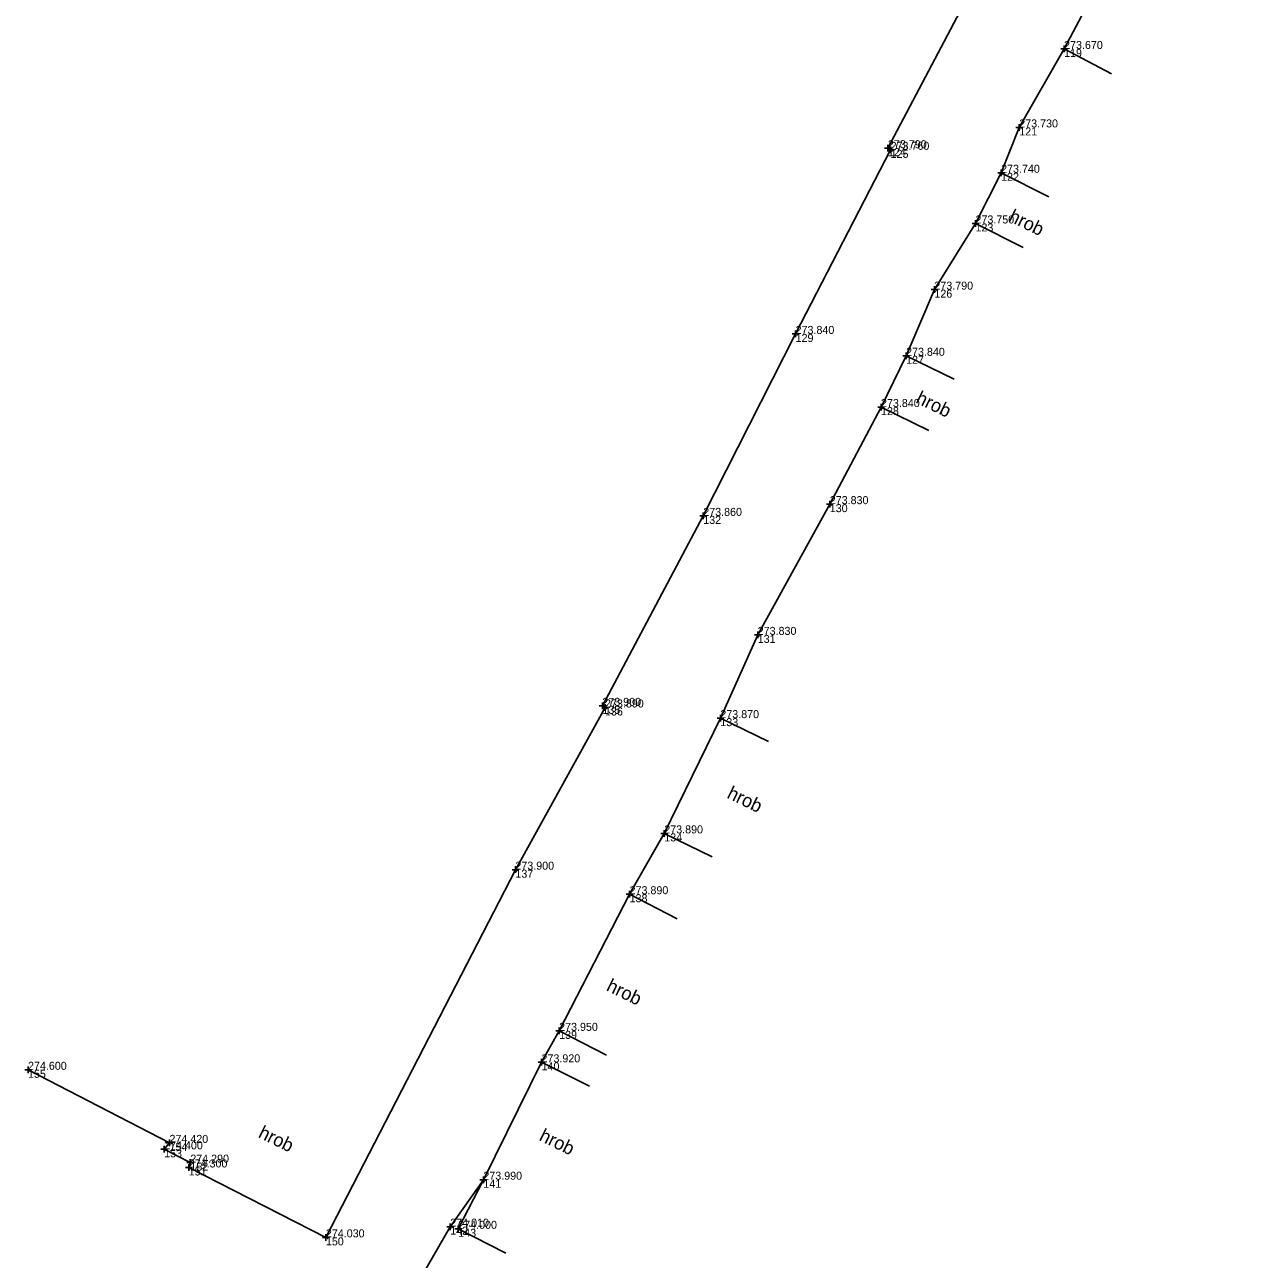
# Model space of a CAD drawing. Extents: x -776606 to -776076, y -974328 to -973875.
# Drawn here: x -776406 to -776383.19, y -974179.42 to -974156.28 of the extents above; entities that cross this region are included whole.
import ezdxf

# ---------------------------------------------------------------- set-up
doc = ezdxf.new("R2010")
doc.units = 0
for name, color, linetype in [('Body polohopisu', 7, 'Continuous'), ('Doplňující texty', 7, 'Continuous'), ('Ploty_opěrné zdi', 7, 'Continuous'), ('Rozhraní ploch', 7, 'Continuous'), ('Výšky bodů', 7, 'Continuous'), ('Čísla bodů', 7, 'Continuous')]:
    doc.layers.add(name, color=color, linetype=linetype)

msp = doc.modelspace()

# ---------------------------------------------------------------- linework, layer by layer
at = {"layer": 'Body polohopisu'}
for p, q in [((-776386.53, -974156.74), (-776386.593, -974156.74)), ((-776386.53, -974156.74), (-776386.53, -974156.677)), ((-776386.53, -974156.74), (-776386.468, -974156.74)), ((-776386.53, -974156.74), (-776386.53, -974156.802)), ((-776387.37, -974158.21), (-776387.432, -974158.21)), ((-776387.37, -974158.21), (-776387.37, -974158.147)), ((-776387.37, -974158.21), (-776387.307, -974158.21)), ((-776387.37, -974158.21), (-776387.37, -974158.272)), ((-776389.83, -974158.6), (-776389.83, -974158.537)), ((-776389.78, -974158.63), (-776389.78, -974158.568)), ((-776389.83, -974158.6), (-776389.892, -974158.6)), ((-776389.78, -974158.63), (-776389.843, -974158.63)), ((-776389.83, -974158.6), (-776389.767, -974158.6)), ((-776389.83, -974158.6), (-776389.83, -974158.662)), ((-776389.78, -974158.63), (-776389.718, -974158.63)), ((-776389.78, -974158.63), (-776389.78, -974158.693)), ((-776387.71, -974159.06), (-776387.71, -974158.998)), ((-776387.71, -974159.06), (-776387.772, -974159.06)), ((-776387.71, -974159.06), (-776387.647, -974159.06)), ((-776387.71, -974159.06), (-776387.71, -974159.123)), ((-776388.19, -974160.01), (-776388.19, -974159.948)), ((-776388.19, -974160.01), (-776388.253, -974160.01)), ((-776388.19, -974160.01), (-776388.128, -974160.01)), ((-776388.19, -974160.01), (-776388.19, -974160.073)), ((-776388.96, -974161.25), (-776389.022, -974161.25)), ((-776388.96, -974161.25), (-776388.96, -974161.188)), ((-776388.96, -974161.25), (-776388.897, -974161.25)), ((-776388.96, -974161.25), (-776388.96, -974161.312)), ((-776391.56, -974162.08), (-776391.56, -974162.018)), ((-776391.56, -974162.08), (-776391.623, -974162.08)), ((-776391.56, -974162.08), (-776391.498, -974162.08)), ((-776391.56, -974162.08), (-776391.56, -974162.143)), ((-776389.49, -974162.49), (-776389.552, -974162.49)), ((-776389.49, -974162.49), (-776389.49, -974162.427)), ((-776389.49, -974162.49), (-776389.427, -974162.49)), ((-776389.49, -974162.49), (-776389.49, -974162.552)), ((-776389.96, -974163.45), (-776390.022, -974163.45)), ((-776389.96, -974163.45), (-776389.96, -974163.388)), ((-776389.96, -974163.45), (-776389.897, -974163.45)), ((-776389.96, -974163.45), (-776389.96, -974163.513)), ((-776390.92, -974165.27), (-776390.983, -974165.27)), ((-776390.92, -974165.27), (-776390.92, -974165.208)), ((-776390.92, -974165.27), (-776390.858, -974165.27)), ((-776390.92, -974165.27), (-776390.92, -974165.333)), ((-776393.29, -974165.49), (-776393.353, -974165.49)), ((-776393.29, -974165.49), (-776393.29, -974165.427)), ((-776393.29, -974165.49), (-776393.228, -974165.49)), ((-776393.29, -974165.49), (-776393.29, -974165.552)), ((-776392.27, -974167.72), (-776392.333, -974167.72)), ((-776392.27, -974167.72), (-776392.27, -974167.657)), ((-776392.27, -974167.72), (-776392.208, -974167.72)), ((-776392.27, -974167.72), (-776392.27, -974167.782)), ((-776395.18, -974169.05), (-776395.18, -974168.988)), ((-776395.18, -974169.05), (-776395.243, -974169.05)), ((-776395.13, -974169.08), (-776395.193, -974169.08)), ((-776395.18, -974169.05), (-776395.118, -974169.05)), ((-776395.18, -974169.05), (-776395.18, -974169.113)), ((-776395.13, -974169.08), (-776395.13, -974169.018)), ((-776395.13, -974169.08), (-776395.068, -974169.08)), ((-776395.13, -974169.08), (-776395.13, -974169.143)), ((-776392.97, -974169.28), (-776392.97, -974169.218)), ((-776392.97, -974169.28), (-776393.032, -974169.28)), ((-776392.97, -974169.28), (-776392.907, -974169.28)), ((-776392.97, -974169.28), (-776392.97, -974169.343)), ((-776394.02, -974171.44), (-776394.083, -974171.44)), ((-776394.02, -974171.44), (-776394.02, -974171.378)), ((-776394.02, -974171.44), (-776393.958, -974171.44)), ((-776394.02, -974171.44), (-776394.02, -974171.503)), ((-776396.81, -974172.12), (-776396.873, -974172.12)), ((-776396.81, -974172.12), (-776396.81, -974172.057)), ((-776396.81, -974172.12), (-776396.748, -974172.12)), ((-776396.81, -974172.12), (-776396.81, -974172.182)), ((-776394.67, -974172.58), (-776394.733, -974172.58)), ((-776394.67, -974172.58), (-776394.67, -974172.518)), ((-776394.67, -974172.58), (-776394.608, -974172.58)), ((-776394.67, -974172.58), (-776394.67, -974172.643)), ((-776395.99, -974175.14), (-776396.052, -974175.14)), ((-776395.99, -974175.14), (-776395.99, -974175.078)), ((-776395.99, -974175.14), (-776395.927, -974175.14)), ((-776395.99, -974175.14), (-776395.99, -974175.203)), ((-776396.32, -974175.73), (-776396.32, -974175.667)), ((-776405.94, -974175.87), (-776406.003, -974175.87)), ((-776405.94, -974175.87), (-776405.94, -974175.807)), ((-776405.94, -974175.87), (-776405.878, -974175.87)), ((-776405.94, -974175.87), (-776405.94, -974175.932)), ((-776396.32, -974175.73), (-776396.383, -974175.73)), ((-776396.32, -974175.73), (-776396.258, -974175.73)), ((-776396.32, -974175.73), (-776396.32, -974175.792)), ((-776403.39, -974177.36), (-776403.39, -974177.297)), ((-776403.29, -974177.24), (-776403.353, -974177.24)), ((-776403.29, -974177.24), (-776403.29, -974177.177)), ((-776403.29, -974177.24), (-776403.228, -974177.24)), ((-776403.29, -974177.24), (-776403.29, -974177.302)), ((-776403.39, -974177.36), (-776403.453, -974177.36)), ((-776403.39, -974177.36), (-776403.328, -974177.36)), ((-776403.39, -974177.36), (-776403.39, -974177.422)), ((-776402.9, -974177.61), (-776402.9, -974177.547)), ((-776402.93, -974177.7), (-776402.993, -974177.7)), ((-776402.9, -974177.61), (-776402.963, -974177.61)), ((-776402.93, -974177.7), (-776402.93, -974177.638)), ((-776402.93, -974177.7), (-776402.868, -974177.7)), ((-776402.93, -974177.7), (-776402.93, -974177.763)), ((-776402.9, -974177.61), (-776402.838, -974177.61)), ((-776402.9, -974177.61), (-776402.9, -974177.672)), ((-776397.41, -974177.93), (-776397.473, -974177.93)), ((-776397.41, -974177.93), (-776397.41, -974177.868)), ((-776397.41, -974177.93), (-776397.348, -974177.93)), ((-776397.41, -974177.93), (-776397.41, -974177.993)), ((-776400.36, -974179.01), (-776400.36, -974178.948)), ((-776398.03, -974178.81), (-776398.093, -974178.81)), ((-776398.03, -974178.81), (-776398.03, -974178.748)), ((-776398.03, -974178.81), (-776397.968, -974178.81)), ((-776398.03, -974178.81), (-776398.03, -974178.873)), ((-776397.88, -974178.85), (-776397.943, -974178.85)), ((-776397.88, -974178.85), (-776397.88, -974178.787)), ((-776397.88, -974178.85), (-776397.818, -974178.85)), ((-776397.88, -974178.85), (-776397.88, -974178.912)), ((-776400.36, -974179.01), (-776400.422, -974179.01)), ((-776400.36, -974179.01), (-776400.297, -974179.01)), ((-776400.36, -974179.01), (-776400.36, -974179.073))]:
    msp.add_line(p, q, dxfattribs=at)
at = {"layer": 'Ploty_opěrné zdi'}
msp.add_lwpolyline([(-776402.9, -974177.61), (-776403.39, -974177.36), (-776403.29, -974177.24)], dxfattribs=at)
at = {"layer": 'Rozhraní ploch'}
for points in [[(-776383.192, -974152.729), (-776384.09, -974152.29), (-776385.39, -974154.95), (-776385.91, -974155.83), (-776386.03, -974155.79), (-776386.53, -974156.74), (-776385.645, -974157.206)], [(-776388.13, -974155.36), (-776389.83, -974158.6), (-776389.78, -974158.63), (-776391.56, -974162.08), (-776393.29, -974165.49), (-776395.18, -974169.05), (-776395.13, -974169.08), (-776396.81, -974172.12), (-776400.36, -974179.01), (-776402.93, -974177.7), (-776402.9, -974177.61)], [(-776386.53, -974156.74), (-776387.37, -974158.21), (-776387.71, -974159.06)], [(-776386.817, -974159.511), (-776387.71, -974159.06), (-776388.19, -974160.01), (-776387.297, -974160.461)], [(-776388.19, -974160.01), (-776388.96, -974161.25), (-776389.49, -974162.49)], [(-776388.592, -974162.93), (-776389.49, -974162.49), (-776389.96, -974163.45), (-776389.062, -974163.89)], [(-776389.96, -974163.45), (-776390.92, -974165.27), (-776392.27, -974167.72), (-776392.97, -974169.28)], [(-776392.071, -974169.717), (-776392.97, -974169.28), (-776394.02, -974171.44), (-776393.121, -974171.877)], [(-776394.02, -974171.44), (-776394.67, -974172.58)], [(-776393.781, -974173.038), (-776394.67, -974172.58), (-776395.99, -974175.14), (-776395.101, -974175.598)], [(-776395.99, -974175.14), (-776396.32, -974175.73)], [(-776403.29, -974177.24), (-776405.94, -974175.87)], [(-776395.424, -974176.174), (-776396.32, -974175.73), (-776397.41, -974177.93), (-776397.88, -974178.85), (-776396.989, -974179.305)], [(-776397.41, -974177.93), (-776398.03, -974178.81), (-776398.76, -974180.08), (-776399.25, -974181.45), (-776399.37, -974182.11), (-776399.96, -974183.42), (-776400.87, -974185.55), (-776400.61, -974185.79)]]:
    msp.add_lwpolyline(points, dxfattribs=at)

# ---------------------------------------------------------------- texts
at = {"layer": 'Doplňující texty'}
for p in [(-776387.586, -974159.957), (-776389.325, -974163.361), (-776392.863, -974170.767), (-776395.123, -974174.377), (-776401.643, -974177.128), (-776396.382, -974177.185)]:
    msp.add_text('hrob', height=0.25, rotation=333.9465, dxfattribs=at).set_placement(p)
at = {"layer": 'Výšky bodů'}
for s, p in [('273.670', (-776386.53, -974156.74)), ('273.730', (-776387.37, -974158.21)), ('273.790', (-776389.83, -974158.6)), ('273.760', (-776389.78, -974158.63)), ('273.740', (-776387.71, -974159.06)), ('273.750', (-776388.19, -974160.01)), ('273.790', (-776388.96, -974161.25)), ('273.840', (-776391.56, -974162.08)), ('273.840', (-776389.49, -974162.49)), ('273.840', (-776389.96, -974163.45)), ('273.830', (-776390.92, -974165.27)), ('273.860', (-776393.29, -974165.49)), ('273.830', (-776392.27, -974167.72)), ('273.900', (-776395.18, -974169.05)), ('273.890', (-776395.13, -974169.08)), ('273.870', (-776392.97, -974169.28)), ('273.890', (-776394.02, -974171.44)), ('273.900', (-776396.81, -974172.12)), ('273.890', (-776394.67, -974172.58)), ('273.950', (-776395.99, -974175.14)), ('273.920', (-776396.32, -974175.73)), ('274.600', (-776405.94, -974175.87)), ('274.420', (-776403.29, -974177.24)), ('274.400', (-776403.39, -974177.36)), ('274.300', (-776402.93, -974177.7)), ('274.290', (-776402.9, -974177.61)), ('273.990', (-776397.41, -974177.93)), ('274.010', (-776398.03, -974178.81)), ('274.000', (-776397.88, -974178.85)), ('274.030', (-776400.36, -974179.01))]:
    msp.add_text(s, height=0.15, dxfattribs=at).set_placement(p)
at = {"layer": 'Čísla bodů'}
for s, p in [('119', (-776386.53, -974156.89)), ('121', (-776387.37, -974158.36)), ('124', (-776389.83, -974158.75)), ('125', (-776389.78, -974158.78)), ('122', (-776387.71, -974159.21)), ('123', (-776388.19, -974160.16)), ('126', (-776388.96, -974161.4)), ('129', (-776391.56, -974162.23)), ('127', (-776389.49, -974162.64)), ('128', (-776389.96, -974163.6)), ('130', (-776390.92, -974165.42)), ('132', (-776393.29, -974165.64)), ('131', (-776392.27, -974167.87)), ('135', (-776395.18, -974169.2)), ('136', (-776395.13, -974169.23)), ('133', (-776392.97, -974169.43)), ('134', (-776394.02, -974171.59)), ('137', (-776396.81, -974172.27)), ('138', (-776394.67, -974172.73)), ('139', (-776395.99, -974175.29)), ('155', (-776405.94, -974176.02)), ('140', (-776396.32, -974175.88)), ('154', (-776403.29, -974177.39)), ('153', (-776403.39, -974177.51)), ('151', (-776402.93, -974177.85)), ('152', (-776402.9, -974177.76)), ('141', (-776397.41, -974178.08)), ('142', (-776398.03, -974178.96)), ('143', (-776397.88, -974179)), ('150', (-776400.36, -974179.16))]:
    msp.add_text(s, height=0.15, dxfattribs=at).set_placement(p)

doc.saveas('drawing.dxf')
